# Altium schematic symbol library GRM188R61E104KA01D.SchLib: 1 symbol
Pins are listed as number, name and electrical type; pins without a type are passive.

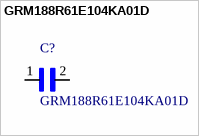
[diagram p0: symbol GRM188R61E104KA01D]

## GRM188R61E104KA01D
designator C?
SMD Capacitor X5R_EIA_ with Capacitance: 0.10uF Tol. 10%. Rated Voltage: 25Vdc; MF: Murata
footprint *CAPC1608X90N
pins: 1, 2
